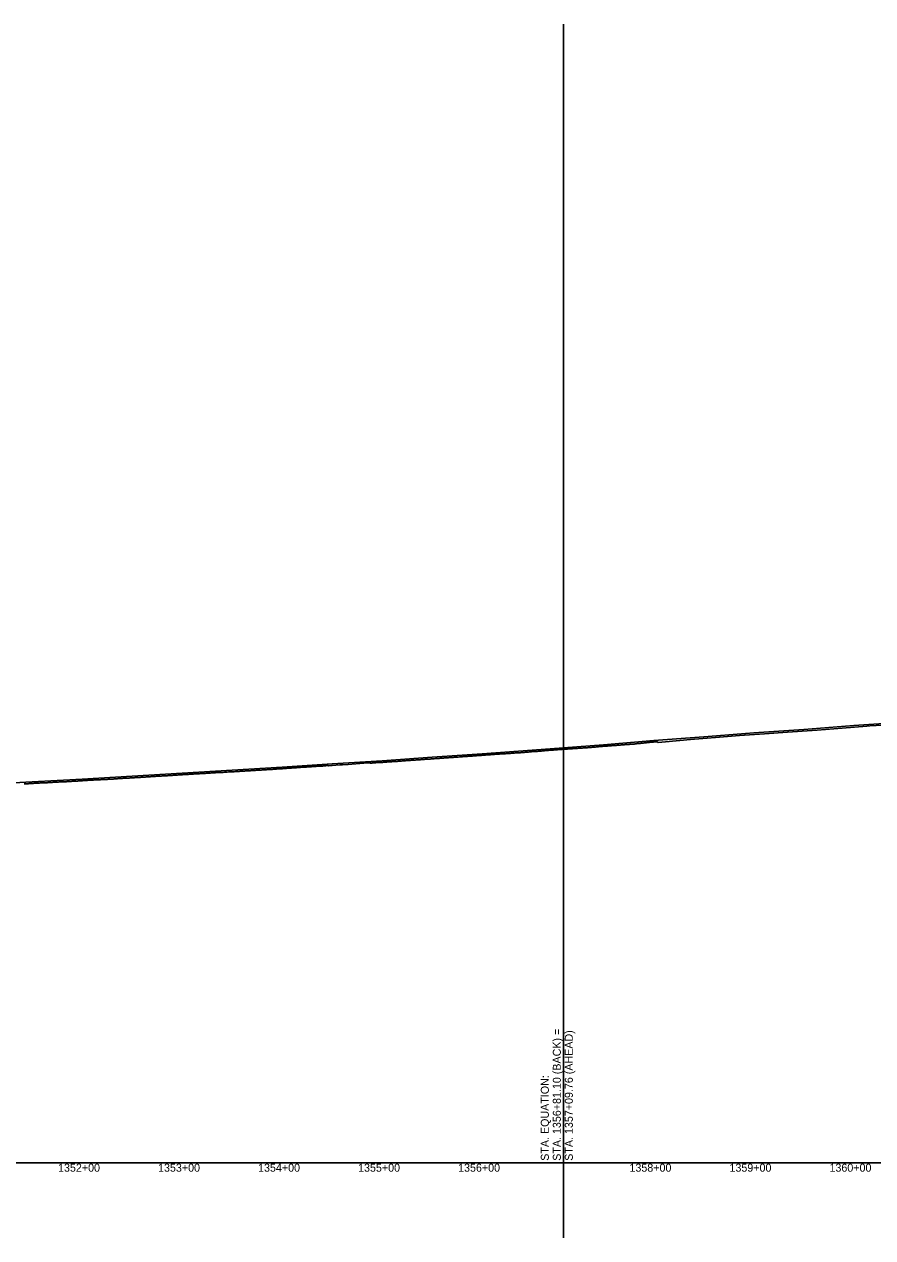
# Model space of a CAD drawing. Extents: x -3793 to 50787, y -1075 to 6138.
# Drawn here: x 22609 to 23458, y -1075 to 138 of the extents above; entities that cross this region are included whole.
import ezdxf

# ---------------------------------------------------------------- set-up
doc = ezdxf.new("R2010")
doc.units = 0
for name, color, linetype in [('RD_DDB_Profile_EX', 7, 'Continuous'), ('RD_DDB_Profile_PR', 7, 'Continuous'), ('RD_DDB_StaTX', 7, 'Continuous'), ('RD_GPK_Profile_Cell', 7, 'Continuous'), ('RD_Sketch10', 7, 'Continuous')]:
    doc.layers.add(name, color=color, linetype=linetype)

msp = doc.modelspace()

# ---------------------------------------------------------------- linework, layer by layer
at = {"layer": 'RD_DDB_Profile_EX'}
for points in [[(23349.282132, -571.19551), (23372.398322, -569.608035), (23397.094964, -567.914425), (23402.097945, -567.52052), (23427.024201, -565.549035), (23451.450188, -563.615915), (23454.694379, -563.405385), (23479.842922, -561.864225)], [(23148.228151, -586.70756), (23149.033519, -586.666715), (23150.029895, -586.576), (23151.034888, -586.53194), (23152.03144, -586.48095), (23153.027189, -586.423985), (23154.023689, -586.323185), (23155.019609, -586.27516), (23156.024515, -586.22745), (23157.020972, -586.123805), (23158.016898, -586.07288), (23159.013148, -586.022015), (23160.00906, -585.971085), (23161.014218, -585.92059), (23162.010573, -585.81749), (23163.009291, -585.76396), (23164.005582, -585.66325), (23165.010823, -585.5647), (23166.006748, -585.515605), (23167.002989, -585.463055), (23167.998801, -585.36378), (23169.004115, -585.313285), (23170.000312, -585.16511), (23170.996223, -585.116505), (23171.99229, -585.1152), (23172.988187, -585.062775), (23173.993585, -584.964145), (23174.989678, -584.863605), (23175.985526, -584.81126), (23176.98143, -584.709795), (23177.990033, -584.608245), (23178.985943, -584.507115), (23179.978918, -584.45656), (23180.98139, -584.3577), (23181.986904, -584.306405), (23182.979876, -584.20588), (23183.982374, -584.1074), (23184.975238, -584.007745), (23185.980838, -583.90724), (23186.983333, -583.857565), (23187.976309, -583.75788), (23188.978775, -583.757695), (23189.984297, -583.657265), (23190.977269, -583.606725), (23191.979761, -583.5074), (23192.98529, -583.406955), (23193.978234, -583.306445), (23194.980722, -583.25712), (23195.983294, -583.15731), (23196.979227, -583.055775), (23197.981689, -583.006415), (23198.974662, -582.85715), (23199.977148, -582.80786), (23200.982685, -582.806555), (23201.97563, -582.70605), (23202.978171, -582.608035), (23203.98371, -582.557085), (23204.976652, -582.50581), (23205.97911, -582.40731), (23206.981672, -582.358025), (23207.977675, -582.256685), (23208.980136, -582.20787), (23209.973107, -582.057735), (23210.975564, -582.05809), (23211.981162, -582.007165), (23212.974129, -581.90743), (23213.976589, -581.85824), (23214.982188, -581.75726), (23215.975078, -581.657495), (23216.977613, -581.558355), (23217.980149, -581.50875), (23218.976103, -581.457175), (23219.978638, -581.308435), (23220.971505, -581.158295), (23221.974067, -581.059615), (23222.979663, -581.00733), (23223.97253, -580.857585), (23224.975091, -580.808425), (23225.97754, -580.659735), (23226.973577, -580.557615), (23227.976115, -580.45892), (23228.978566, -580.30985), (23229.974601, -580.207975), (23230.977064, -580.15856), (23231.979593, -580.059935), (23232.972569, -579.95892), (23233.97809, -579.857465), (23234.971029, -579.757705), (23235.973513, -579.659805), (23236.976046, -579.559475), (23237.971985, -579.458065), (23238.974539, -579.359425), (23239.977072, -579.26045), (23240.96831, -579.208045), (23241.970239, -579.158735), (23243.006602, -579.80086), (23250.24315, -579.18648), (23275.219645, -577.06756), (23300.205689, -574.94572), (23324.27281, -573.10614), (23349.282132, -571.19551)], [(23010.133224, -596.73972), (23011.134564, -596.69841), (23012.362765, -596.584525), (23013.131623, -596.507795), (23014.126339, -596.449705), (23015.127495, -596.441495), (23016.123104, -596.35075), (23017.12427, -596.3009), (23018.118885, -596.20939), (23019.122598, -596.175955), (23020.320424, -596.097725), (23021.12126, -596.033745), (23022.119693, -595.95), (23023.12625, -595.87522), (23024.127215, -595.77533), (23025.127245, -595.66689), (23026.125675, -595.61671), (23027.124105, -595.51653), (23028.278084, -595.458575), (23029.130526, -595.424495), (23030.128761, -595.357325), (23031.129509, -595.31605), (23032.1294, -595.207345), (23033.127639, -595.140045), (23034.134453, -595.10687), (23035.131005, -595.02405), (23036.235743, -594.920015), (23037.128345, -594.847955), (23038.128895, -594.80692), (23039.135492, -594.68068), (23040.134056, -594.656645), (23041.132091, -594.57392), (23042.130656, -594.473905), (23043.128693, -594.465115), (23044.193403, -594.3911), (23045.136184, -594.29789), (23046.134028, -594.206515), (23047.132402, -594.14785), (23048.130246, -594.097785), (23049.126932, -594.00656), (23050.13332, -593.956375), (23051.131161, -593.89758), (23052.151062, -593.78753), (23053.130264, -593.698185), (23054.127918, -593.615455), (23055.126101, -593.56552), (23056.131777, -593.51535), (23057.129964, -593.46541), (23058.128148, -593.398215), (23059.128345, -593.26579), (23060.126521, -593.17439), (23061.132552, -593.165795), (23062.130021, -593.08292), (23063.126366, -593.03299), (23064.123836, -592.98301), (23065.121831, -592.9), (23066.127867, -592.808485), (23067.125339, -592.774575), (23068.123323, -592.683105), (23069.123704, -592.583335), (23070.129056, -592.47494), (23071.126866, -592.416735), (23072.124157, -592.31682), (23073.121961, -592.266965), (23074.11976, -592.16711), (23075.125134, -592.10878), (23076.122409, -592.025335), (23077.120031, -591.98365), (23078.117142, -591.92557), (23079.122349, -591.85923), (23080.119466, -591.751265), (23081.118149, -591.667605), (23082.115761, -591.61779), (23083.11287, -591.53396), (23084.118077, -591.48394), (23085.117638, -591.42627), (23086.114579, -591.334265), (23087.11152, -591.28435), (23088.11861, -591.20782), (23089.115549, -591.165555), (23090.112487, -591.11547), (23091.109425, -591.092305), (23092.106334, -591.00765), (23093.111282, -590.91528), (23094.109992, -590.87274), (23095.106751, -590.78011), (23096.10351, -590.722425), (23097.108491, -590.707465), (23098.10526, -590.62224), (23099.102029, -590.50152), (23100.100628, -590.436495), (23101.099866, -590.364315), (23102.104734, -590.307135), (23103.101329, -590.257075), (23104.097924, -590.15701), (23105.094952, -590.15), (23106.101201, -590.05), (23107.097792, -589.96372), (23108.094341, -589.913585), (23109.090759, -589.82016), (23110.087176, -589.706645)], [(23110.087176, -589.706645), (23111.092387, -589.656605), (23112.090075, -589.563075), (23113.086488, -589.493535), (23114.082901, -589.437215), (23115.079314, -589.35), (23116.086869, -589.23759), (23117.084312, -589.1), (23118.080557, -589.05), (23119.077583, -588.961955), (23120.082331, -588.955935), (23121.078582, -588.84415), (23122.075587, -588.8), (23123.071826, -588.7057), (23124.069099, -588.65), (23125.07339, -588.588845), (23126.070523, -588.45), (23127.066578, -588.38382), (23128.062304, -588.334075), (23129.068024, -588.23421), (23130.064085, -588.09483), (23131.060813, -588.02965), (23132.059623, -587.935285), (23133.05652, -587.88076), (23134.060926, -587.77619), (23135.0569, -587.722035), (23136.053756, -587.577175), (23137.049434, -587.536585), (23138.055061, -587.49558), (23139.051021, -587.382725), (23140.047798, -587.287335), (23141.043486, -587.19587), (23142.039433, -587.141945), (23143.045053, -587.04205), (23144.040761, -586.99612), (23145.037447, -586.946215), (23146.033381, -586.85736), (23147.041627, -586.81064), (23148.228151, -586.70756)], [(22786.981368, -610.993545), (22787.976143, -610.932655), (22788.977658, -610.871165), (22789.974372, -610.78252), (22790.975882, -610.70471), (22791.98431, -610.67225), (22792.979086, -610.54488), (22793.982533, -610.54457), (22794.977309, -610.48391), (22795.980755, -610.43358), (22796.976632, -610.345355), (22797.980079, -610.32299), (22798.974849, -610.284645), (22799.978295, -610.18447), (22800.973065, -610.04606), (22801.977604, -609.99617), (22803.199014, -609.984845), (22803.974728, -609.946285), (22805.463615, -609.8716), (22805.973756, -609.846315), (22806.9772, -609.829235), (22807.976658, -609.7911), (22809.195873, -609.658305), (22809.980571, -609.61919), (22811.194533, -609.55854), (22811.9757, -609.518565), (22813.421275, -609.435435), (22813.974723, -609.40792), (22815.196584, -609.30781), (22816.191563, -609.24729), (22816.9761, -609.20829), (22818.187682, -609.197995), (22818.973232, -609.1198), (22820.193516, -609.030555), (22820.972247, -608.952705), (22821.378934, -608.93247), (22822.191574, -608.88108), (22822.971256, -608.80321), (22824.189369, -608.78175), (22824.977075, -608.742655), (22826.187149, -608.64311), (22826.97608, -608.60394), (22828.190496, -608.53277), (22828.973236, -608.454595), (22829.336594, -608.436555), (22830.188092, -608.415305), (22831.182595, -608.34466), (22831.974634, -608.30541), (22833.187601, -608.25557), (22833.973628, -608.21659), (22835.184918, -608.106325), (22835.97261, -608.067265), (22837.294254, -607.9706), (22837.976692, -607.93691), (22839.177093, -607.887715), (22840.179709, -607.788175), (22841.181691, -607.76814), (22841.974668, -607.68926), (22843.178525, -607.67975), (22843.973633, -607.640245), (22845.251913, -607.513225), (22845.975556, -607.440425), (22847.167293, -607.37178), (22847.972805, -607.332155), (22849.17208, -607.273155), (22850.171371, -607.19222), (22851.16936, -607.14209), (22852.169258, -607.082015), (22853.209573, -607.039325), (22854.17605, -606.98088), (22855.175123, -606.930525), (22856.172881, -606.880515), (22857.172575, -606.79035), (22858.171646, -606.690025), (22859.171343, -606.589905), (22860.171041, -606.50982), (22861.17592, -606.499195), (22862.175414, -606.399195), (22863.174908, -606.33911), (22864.173768, -606.288905), (22865.173263, -606.328805), (22866.170161, -606.188815), (22867.169656, -606.119135), (22868.176893, -606.039105), (22869.17574, -605.958495), (22870.175035, -605.85859), (22870.970702, -605.818695), (22872.17354, -605.759355), (22873.172831, -605.699385), (22874.17212, -605.65954), (22875.178515, -605.5591), (22876.175854, -605.499205), (22877.174487, -605.36931), (22878.173581, -605.27954), (22879.172672, -605.259595), (22880.171125, -605.189745), (22881.168273, -605.129915), (22882.175104, -605.06974), (22883.173557, -604.96976), (22884.172651, -604.879935), (22885.171715, -604.80006)], [(22885.171715, -604.80006), (22886.16997, -604.750125), (22887.16759, -604.720155), (22888.167777, -604.630155), (22889.173139, -604.569815), (22890.172696, -604.51969), (22891.170951, -604.47982), (22892.170511, -604.399795), (22893.168731, -604.349865), (22894.173298, -604.29928), (22895.168181, -604.20916), (22896.175921, -604.128335), (22897.170804, -604.098475), (22898.178544, -604.008675), (22899.173427, -603.97721), (22900.180505, -603.966445), (22901.176007, -603.876565), (22902.180376, -603.715225), (22903.178235, -603.6838), (22904.182605, -603.582625), (22905.179788, -603.504095), (22906.184833, -603.49256), (22907.182012, -603.471245), (22907.969161, -603.391865), (22908.91319, -603.352255), (22909.535182, -603.35222), (22910.310693, -603.351895), (22911.097927, -603.07819), (22911.871186, -603.078115), (22912.645118, -603.077965), (22913.42841, -603.117055), (22916.517387, -602.90582), (22916.87085, -602.8821), (22924.828509, -602.349145), (22927.378459, -602.178705), (22933.062401, -601.791515), (22940.743828, -601.279085), (22948.701488, -600.74933), (22954.185631, -600.42618), (22955.184499, -600.515935), (22956.185541, -600.515535), (22956.659147, -600.468565), (22957.183596, -600.416375), (22958.185163, -600.210895), (22959.180661, -600.249795), (22960.184695, -600.2004), (22961.180179, -600.10044), (22962.183528, -600.06188), (22963.179697, -600.040095), (22964.180585, -600.039865), (22964.616807, -599.95278), (22965.179109, -599.8627), (22966.179823, -599.79537), (22967.177563, -599.82412), (22968.178979, -599.7525), (22969.176707, -599.67477), (22970.178136, -599.546295), (22971.173368, -599.47492), (22972.176615, -599.403995), (22972.574467, -599.364025), (22973.172393, -599.33624), (22974.175479, -599.315535), (22975.171154, -599.25538), (22976.174269, -599.176885), (22977.169257, -599.027065), (22978.170541, -598.93758), (22979.168025, -598.85878), (22980.161642, -598.798745), (22980.532126, -598.817305), (22981.166674, -598.8287), (22982.159457, -598.82903), (22983.162547, -598.68926), (22984.15785, -598.58997), (22985.160932, -598.50005), (22986.156244, -598.440775), (22987.158694, -598.39076), (22988.154637, -598.30132), (22988.489786, -598.2846), (22989.156963, -598.241605), (22990.150172, -598.15171), (22991.154985, -598.08296), (22992.147583, -598.073835), (22993.153006, -597.993465), (22994.145604, -597.93444), (22995.148458, -597.843955), (22996.141053, -597.73501), (22996.447445, -597.71998), (22997.14576, -597.66724), (22998.147257, -597.576445), (22999.142636, -597.526705), (23000.146706, -597.47731), (23001.140291, -597.418605), (23002.141797, -597.286705), (23003.139673, -597.2464), (23004.405105, -597.13761), (23005.1346, -597.120075), (23006.140199, -597.0296), (23007.132994, -596.988665), (23008.134326, -596.897505), (23009.130213, -596.789685), (23010.133224, -596.73972)], [(22608.995031, -621.338385), (22609.995126, -621.279215), (22610.993313, -621.23962), (22611.99554, -621.158315), (22612.993732, -621.10836), (22613.996988, -621.058275), (22614.479785, -621.03409), (22614.994132, -620.99783), (22615.999171, -620.89772), (22616.9916, -620.826535), (22617.995595, -620.765715), (22618.993778, -620.726405), (22619.996991, -620.686855), (22620.994129, -620.63687), (22621.99734, -620.576275), (22622.437445, -620.53221), (22622.994465, -620.507905), (22623.995559, -620.496965), (22624.991888, -620.40775), (22625.99585, -620.38644), (22626.994017, -620.38664), (22627.997197, -620.32608), (22628.994312, -620.255085), (22629.999325, -620.16554), (22630.395104, -620.165385), (22630.991725, -620.154785), (22631.995662, -620.136405), (22632.991968, -620.04728), (22633.996956, -619.97619), (22634.993263, -619.908045), (22635.996432, -619.897615), (22636.994557, -619.8374), (22637.993798, -619.75802), (22638.352764, -619.740085), (22638.991906, -619.718665), (22639.995059, -619.668735), (22640.991346, -619.61893), (22641.996311, -619.527585), (22642.988654, -619.477535), (22643.989688, -619.3771), (22644.992845, -619.37725), (22645.992063, -619.339555), (22646.310424, -619.33956), (22646.998051, -619.329185), (22647.990376, -619.237585), (22648.989578, -619.179115), (22649.994519, -619.17916), (22650.993717, -619.10816), (22651.987866, -618.99766), (22652.990989, -618.997825), (22654.268083, -618.883635), (22654.991187, -618.8369), (22655.994286, -618.816205), (22656.988416, -618.74529), (22657.991518, -618.666575), (22658.990693, -618.616345), (22659.991685, -618.576525), (22660.994789, -618.505915), (22662.225743, -618.44251), (22662.988074, -618.387175), (22663.991162, -618.3354), (22664.992128, -618.285085), (22665.991281, -618.195355), (22666.98751, -618.10667), (22667.988471, -618.06482), (22668.991575, -618.015495), (22670.183402, -617.92626), (22670.991675, -617.875385), (22671.988913, -617.787115), (22672.989845, -617.747195), (22673.988992, -617.697115), (22674.992099, -617.63751), (22675.993024, -617.59755), (22676.986033, -617.557845), (22678.141062, -617.52096), (22678.988772, -617.42698), (22679.992624, -617.34792), (22680.992511, -617.318125), (22681.98626, -617.228265), (22682.990107, -617.16837), (22683.989997, -617.15793), (22684.988866, -617.10753), (22686.098721, -617.05165), (22686.986484, -617.01681)], [(22686.986484, -617.01681), (22687.985325, -617.0061), (22688.9852, -616.955955), (22689.991931, -616.905435), (22690.991804, -616.85529), (22691.990624, -616.79442), (22692.992329, -616.712395), (22694.056381, -616.669565), (22694.991003, -616.61186), (22695.990861, -616.561785), (22696.9868, -616.52151), (22697.987452, -616.47108), (22698.987311, -616.41026), (22699.987169, -616.310185), (22700.987028, -616.220875), (22702.014041, -616.156965), (22702.98753, -616.0597), (22703.987373, -616.00976), (22704.986143, -615.95957), (22705.988882, -615.908185), (22706.988726, -615.81915), (22707.987482, -615.758055), (22708.989221, -615.74704), (22709.989064, -615.69711), (22710.987806, -615.5689), (22711.987637, -615.4909), (22712.987468, -615.491055), (22713.989188, -615.44109), (22714.987934, -615.35194), (22715.983878, -615.2624), (22716.983706, -615.201585), (22717.982447, -615.19061), (22718.98416, -615.140755), (22719.983973, -615.09101), (22720.982705, -615.03018), (22721.98252, -614.980465), (22722.989126, -614.91941), (22723.989748, -614.83023), (22724.989566, -614.780515), (22725.98549, -614.701845), (22726.984211, -614.64111), (22727.986903, -614.601315), (22728.986712, -614.551645), (22729.983444, -614.451055), (22730.983246, -614.40138), (22731.985941, -614.311735), (22732.985746, -614.24003), (22733.980575, -614.18951), (22734.989045, -614.139445), (22735.984967, -614.078135), (22736.979791, -613.966535), (22737.986332, -613.916605), (22738.982258, -613.866325), (22739.982876, -613.82763), (22740.985549, -613.765735), (22741.985341, -613.732895), (22742.980152, -613.64358), (22743.986676, -613.56612), (22744.984535, -613.515825), (22745.983207, -613.455125), (22746.979127, -613.40496), (22747.985652, -613.35517), (22748.980461, -613.26592), (22749.982177, -613.26649), (22750.984832, -613.227145), (22751.984605, -613.12788), (22752.979408, -613.027635), (22753.985933, -612.939025), (22754.983766, -612.888885), (22755.982434, -612.878295), (22756.985091, -612.777825), (22757.984867, -612.717555), (22758.979661, -612.71741), (22759.984233, -612.61688), (22760.983996, -612.56781), (22761.97879, -612.478695), (22762.985324, -612.40108), (22763.980117, -612.32897), (22764.98179, -612.30782), (22765.976583, -612.21865), (22766.983931, -612.179775), (22767.978718, -612.096965), (22768.982179, -612.09622), (22769.978058, -612.00744), (22770.981525, -611.956745), (22771.976312, -611.834685), (22772.979778, -611.783885), (22773.981313, -611.73331), (22774.978023, -611.68327), (22775.984532, -611.634135), (22776.981232, -611.595155), (22777.982767, -611.544715), (22778.979473, -611.433585), (22779.981002, -611.38311), (22780.978818, -611.33337), (22781.980346, -611.244095), (22782.983798, -611.19364), (22783.978575, -611.105055), (22784.982027, -611.08227), (22785.977913, -611.032855), (22786.981368, -610.993545)]]:
    msp.add_lwpolyline(points, dxfattribs=at)
at = {"layer": 'RD_DDB_Profile_PR'}
for points in [[(23148.23, -585.170077), (23188.47, -582.158), (23238.47, -577.809), (23288.47, -574.3425), (23338.47, -570.4215), (23388.47, -566.906), (23438.47, -563.0435), (23488.47, -559.72)], [(22567.13, -622.029), (22617.13, -619.2185), (22667.13, -616.501), (22717.13, -613.6), (22767.13, -610.568), (22817.13, -607.607), (22867.13, -604.522), (22917.13, -601.265), (22967.13, -598.2225), (23017.13, -594.701), (23067.13, -591.1745), (23117.13, -587.498), (23148.23, -585.170077)]]:
    msp.add_lwpolyline(points, dxfattribs=at)
at = {"layer": 'RD_GPK_Profile_Cell'}
msp.add_line((1000, -1000), (46610.921919, -1000), dxfattribs=at)
at = {"layer": 'RD_Sketch10'}
for q in [(23148.23, 138.027692), (23148.23, -1075)]:
    msp.add_line((23148.23, -1000), q, dxfattribs=at)

# ---------------------------------------------------------------- texts
at = {"layer": 'RD_DDB_StaTX'}
for s, p in [('1352+00', (22642.921023, -1009)), ('1352+00', (22642.925471, -1009)), ('1353+00', (22742.921023, -1009)), ('1353+00', (22742.925471, -1009)), ('1354+00', (22842.921023, -1009)), ('1354+00', (22842.925471, -1009)), ('1355+00', (22942.921023, -1009)), ('1355+00', (22942.925471, -1009)), ('1356+00', (23042.921023, -1009)), ('1356+00', (23042.925471, -1009)), ('1358+00', (23214.263622, -1009)), ('1358+00', (23214.265471, -1009)), ('1359+00', (23314.263622, -1009)), ('1359+00', (23314.265471, -1009)), ('1360+00', (23414.263622, -1009)), ('1360+00', (23414.265471, -1009))]:
    msp.add_text(s, height=8, dxfattribs=at).set_placement(p)
at = {"layer": 'RD_Sketch10'}
for s, p in [('STA. 1356+81.10 (BACK) =', (23145.640055, -998.095817)), ('STA. 1357+09.76 (AHEAD)', (23157.640055, -998.095817)), ('STA. EQUATION:', (23133.640055, -998.095817))]:
    msp.add_text(s, height=8, rotation=90, dxfattribs=at).set_placement(p)

doc.saveas('drawing.dxf')
